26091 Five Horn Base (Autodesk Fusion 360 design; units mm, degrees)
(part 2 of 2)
sketch "Bell Flange Profile" plane through (0, -19.8438, 0) normal (0, -1, 0) x axis (1, 0, 0)
  line L1 (0, 180.975) -> (3.175, 180.975)
  line L2 (0, 176.6094) -> (0, 180.975)
  line L3 (0, 158.8492) -> (0, 166.2906)
  line L4 (0, 108.7438) -> (0, 114.2008)
  line L5 (0, 98.425) -> (0, 100.8063)
  line L6 (2.6536, 98.425) -> (0, 98.425)
  line L7 (14.1513, 108.6076) -> (4.8987, 99.3549)
  line L8 (30.2459, 109.5375) -> (16.3964, 109.5375)
  line L9 (29.9633, 130.2242) -> (35.0084, 127.3114)
  line L10 (9.525, 174.625) -> (9.525, 165.6244)
  line L11 (42.8463, 117.475) -> (42.8463, 114.3)
  line L12 (103.1875, 114.3) -> (42.8463, 114.3)
  line L13 (103.1875, 114.3) -> (103.1875, 117.475)
  line L14 (42.8463, 117.475) -> (103.1875, 117.475)
  curve K1 (39.6962, 120.2531) -> (39.0914, 115.5292)
  line L15 (42.8463, 117.475) -> (42.8463, 114.3)
  line L16 (39.6378, 117.475) -> (42.8463, 117.475)
  line L17 (0, 85.725) -> (0, 98.425)
  line L18 (53.975, 85.725) -> (0, 85.725)
  line L19 (53.975, 117.475) -> (53.975, 85.725)
  circle C1 centre (30.2459, 119.0625) radius 5.1594
  arc A1 centre (3.175, 174.625) radius 6.35 clockwise from (3.175, 180.975) to (9.525, 174.625)
  arc A2 centre (0, 171.45) radius 5.1594 clockwise from (0, 176.6094) to (0, 166.2906)
  arc A3 centre (0, 136.525) radius 22.3242 clockwise from (0, 158.8492) to (0, 114.2008)
  arc A4 centre (0, 104.775) radius 3.9687 clockwise from (0, 108.7438) to (0, 100.8063)
  arc A5 centre (2.6536, 101.6) radius 3.175 clockwise from (4.8987, 99.3549) to (2.6536, 98.425)
  arc A6 centre (16.3964, 106.3625) radius 3.175 clockwise from (14.1513, 108.6076) to (16.3964, 109.5375)
  arc A7 centre (30.2459, 119.0625) radius 9.525 clockwise from (35.0084, 127.3114) to (30.2459, 109.5375)
  arc A8 centre (31.5508, 132.9738) radius 3.175 clockwise from (29.9633, 130.2242) to (28.3957, 133.329)
  arc A9 centre (0, 136.525) radius 28.575 clockwise from (11.43, 162.7144) to (28.3957, 133.329)
  arc A10 centre (12.7, 165.6244) radius 3.175 clockwise from (11.43, 162.7144) to (9.525, 165.6244)
  arc A11 centre (42.8463, 120.65) radius 6.35 clockwise from (42.8463, 114.3) to (39.0914, 115.5292)
  arc A12 centre (42.8463, 120.65) radius 3.175 clockwise from (42.8463, 117.475) to (39.6962, 120.2531)
  point P32 (42.8463, 117.475)
  point P40 (42.8463, 117.475)
  point P41 (39.6378, 117.475)
  point P16 (0, 98.425)
  point P42 (0, 98.425)
  point P45 (53.975, 117.475)
  point P12 (0, 136.525)
  point P43 (0, 85.725)
  coincident P32 P40
  coincident K1 P41
  horizontal L16
  coincident P16 P42
  perpendicular L6 L17
  perpendicular L17 L18
  coincident L14 P45
  perpendicular L14 L19
  dimension "d247" distance P12 P43 = 50.8
  dimension "d248" distance P12 L19 = 53.975 (= "2 1/8")
extrude "Extrude16" add sketch "Bell Flange Profile" profile of L6 A5 L7 A6 L8 A7 L11 L12 L14 K1 A11 L15 A12 L16 L17 L18 L19 blind -6.35 from offset -1.5875 (= "( -1 / 16 ) * 1 in")
fillet "Fillet20" radius 3.175
fillet "Fillet23" radius 0.7937 (= "( 1 / 32 ) * 1 in")
fillet "Fillet24" radius 0.7937 (= "( 1 / 32 ) * 1 in")
fillet "Fillet25" radius 0.3969 (= "( 1 / 64 ) * 1 in")
fillet "Fillet13" radius 1.5875 (= "( 1 / 16 ) * 1 in")
fillet "Fillet15" radius 1.587
fillet "Fillet29" radius 2.381
fillet "Fillet30" radius 1.5875 (= "( 1 / 16 ) * 1 in")
fillet "Fillet31" radius 0.7937 (= "( 1 / 32 ) * 1 in")
mirror "Mirror3" mirrorStitchTolerance 0.1016
delete_face "DeleteFace2"
mirror "Mirror4" mirrorStitchTolerance 0.1016
fillet "Fillet16" radius 1.5875 (= "( 1 / 16 ) * 1 in")
extrude "Extrude11" cut sketch "Bottom Profile" profile of C3 C4 C5 C6 against normal blind 17.4752
offset_faces "OffsetFaces1"
fillet "Fillet18" radius 1.5875 (= "( 1 / 16 ) * 1 in")
sketch "Piping Profile 1" plane through (0, 0, 0) normal (0, 0, -1) x axis (1, 0, 0)
  circle C1 centre (-26.9408, -26.9408) radius 7.1437
  circle C2 centre (26.9408, -26.9408) radius 7.1437
  circle C3 centre (-26.9408, 26.9408) radius 7.1437
  circle C4 centre (26.9408, 26.9408) radius 7.1437
  circle C5 centre (0, 0) radius 50.8
  circle C6 centre (0, 0) radius 9.1281
  circle C7 centre (0, 0) radius 7.1437
  point P1 (0, 0)
  point P7 (0, 0)
  point P8 (0, 0)
  coincident P1 P7
  coincident P1 P8
  dimension "d224" diameter C6 = 18.2563
  dimension "d225" diameter C7 = 14.2875 (= "( 9 / 16 ) * 1 in")
extrude "Extrude12" cut sketch "Piping Profile 1" profile of C6 C7 against normal blind 19.05 (magnitude of "( -3 / 4 ) * 1 in")
extrude "Extrude13" cut sketch "Piping Profile 1" profile of C7 against normal blind 104.775 (magnitude of "-4 1/8")
chamfer "Chamfer1" distance 0.3969 (= "( 1 / 64 ) * 1 in")
sketch "Piping Profile 2" plane through (-303.2959, 0, 0) normal (-1, 0, 0) x axis (0, -1, 0)
  line L1 (-14.2875, 119.0625) -> (14.2875, 119.0625)
  line L2 (-14.2875, 82.55) -> (-14.2875, 119.0625)
  line L3 (14.2875, 82.55) -> (-14.2875, 82.55)
  line L4 (14.2875, 119.0625) -> (14.2875, 82.55)
  line L5 (-17.4625, 82.55) -> (-17.4625, 108.9912)
  line L6 (-17.4625, 82.55) -> (-14.2875, 82.55)
  line L7 (-14.2875, 119.0625) -> (-14.2875, 82.55)
  line L8 (-14.2875, 82.55) -> (-14.2875, 79.375)
  line L9 (-17.4625, 82.55) -> (-14.2875, 82.55)
  line L10 (-14.2875, 82.55) -> (14.2875, 82.55)
  line L11 (-14.2875, 82.55) -> (-14.2875, 79.375)
  line L12 (14.2875, 79.375) -> (-14.2875, 79.375)
  line L13 (14.2875, 82.55) -> (14.2875, 79.375)
  line L14 (14.2875, 82.55) -> (14.2875, 119.0625)
  line L15 (17.4625, 82.55) -> (14.2875, 82.55)
  line L16 (17.4625, 108.9912) -> (17.4625, 82.55)
  line L17 (17.4625, 82.55) -> (14.2875, 82.55)
  line L18 (14.2875, 82.55) -> (14.2875, 79.375)
  line L19 (19.8438, 109.5375) -> (19.8438, 127.3114)
  line L20 (3.6404, 127.3114) -> (19.8438, 127.3114)
  curve K1 (2.3812, 126.9064) -> (3.6404, 127.3114)
  line L21 (-2.3812, 126.9064) -> (2.3812, 126.9064)
  curve K2 (-2.3812, 126.9064) -> (-3.6404, 127.3114)
  line L22 (-19.8438, 127.3114) -> (-3.6404, 127.3114)
  line L23 (-19.8438, 109.5375) -> (-19.8438, 127.3114)
  line L24 (14.2875, 119.0625) -> (-14.2875, 119.0625)
  line L25 (0, 119.0625) -> (0, 79.375)
  curve K3 (-14.2875, 119.0625) -> (-17.4625, 108.9912)
  curve K4 (14.2875, 119.0625) -> (17.4625, 108.9912)
  curve K5 (19.8435, 111.0053) -> (14.2875, 119.0625)
  curve K6 (-19.8435, 111.0053) -> (-14.2875, 119.0625)
  line L26 (19.8435, 111.0053) -> (19.8435, 109.5375)
  line L27 (19.8438, 109.5375) -> (19.8435, 109.5375)
  line L28 (-19.8435, 109.5375) -> (-19.8438, 109.5375)
  line L29 (-19.8435, 111.0053) -> (-19.8435, 109.5375)
  arc A1 centre (-14.2875, 82.55) radius 3.175 clockwise from (-14.2875, 79.375) to (-17.4625, 82.55)
  arc A2 centre (14.2875, 82.55) radius 3.175 clockwise from (17.4625, 82.55) to (14.2875, 79.375)
  circle C1 centre (0, 101.6) radius 7.1437
  point P34 (0, 79.375)
  point P36 (0, 101.6)
  point P35 (0, 119.0625)
  midpoint L12 P34
  perpendicular L10 L25
  coincident L25 P36
  coincident L24 P35
  dimension "d231" diameter C1 = 14.2875 (= "( 9 / 16 ) * 1 in")
  dimension "d232" distance L12 P36 = 22.225 (= "( 7 / 8 ) * 1 in")
extrude "Extrude14" cut sketch "Piping Profile 2" profile of C1 against normal blind 606.6028
sketch "Piping Profile 3" plane through (0, 0, 0) normal (0, 0, -1) x axis (1, 0, 0)
  line L1 (-95.0806, 35.279) -> (-31.1922, 42.6427)
  line L2 (-111.1939, 47.7175) -> (-101.7641, 37.7185)
  line L3 (-125.0095, 49.2125) -> (-114.6586, 49.2125)
  line L4 (-133.6665, 35.1345) -> (-129.4584, 46.1496)
  line L5 (-136.5547, -31.4469) -> (-136.5547, 31.4469)
  line L6 (-129.4584, -46.1496) -> (-133.6665, -35.1345)
  line L7 (-114.6586, -49.2125) -> (-125.0095, -49.2125)
  line L8 (-101.7641, -37.7185) -> (-111.1939, -47.7175)
  line L9 (-31.1922, -42.6427) -> (-95.0806, -35.279)
  line L10 (95.0806, -35.279) -> (31.1922, -42.6427)
  line L11 (111.1939, -47.7175) -> (101.7641, -37.7185)
  line L12 (125.0095, -49.2125) -> (114.6586, -49.2125)
  line L13 (133.6665, -35.1345) -> (129.4584, -46.1496)
  line L14 (136.5547, 31.4469) -> (136.5547, -31.4469)
  line L15 (129.4584, 46.1496) -> (133.6665, 35.1345)
  line L16 (114.6586, 49.2125) -> (125.0095, 49.2125)
  line L17 (101.7641, 37.7185) -> (111.1939, 47.7175)
  line L18 (31.1922, 42.6427) -> (95.0806, 35.279)
  line L19 (120.65, 0) -> (0, 0)
  line L20 (-120.65, 0) -> (0, 0)
  circle C1 centre (0, 0) radius 50.8
  circle C2 centre (26.9408, 26.9408) radius 7.1437
  circle C3 centre (-26.9408, 26.9408) radius 7.1437
  circle C4 centre (26.9408, -26.9408) radius 7.1437
  circle C5 centre (-26.9408, -26.9408) radius 7.1437
  circle C6 centre (0, 0) radius 9.525
  arc A1 centre (0, 0) radius 52.8332 clockwise from (-31.1922, -42.6427) to (-31.1922, 42.6427)
  arc A2 centre (-95.9895, 43.1643) radius 7.9375 clockwise from (-95.0806, 35.279) to (-101.7641, 37.7185)
  arc A3 centre (-114.6586, 44.45) radius 4.7625 clockwise from (-114.6586, 49.2125) to (-111.1939, 47.7175)
  arc A4 centre (-125.0095, 44.45) radius 4.7625 clockwise from (-129.4584, 46.1496) to (-125.0095, 49.2125)
  arc A5 centre (-141.0813, 37.9671) radius 7.9375 clockwise from (-133.6665, 35.1345) to (-136.5547, 31.4469)
  arc A6 centre (-141.0813, -37.9671) radius 7.9375 clockwise from (-136.5547, -31.4469) to (-133.6665, -35.1345)
  arc A7 centre (-125.0095, -44.45) radius 4.7625 clockwise from (-125.0095, -49.2125) to (-129.4584, -46.1496)
  arc A8 centre (-114.6586, -44.45) radius 4.7625 clockwise from (-111.1939, -47.7175) to (-114.6586, -49.2125)
  arc A9 centre (-95.9895, -43.1643) radius 7.9375 clockwise from (-101.7641, -37.7185) to (-95.0806, -35.279)
  arc A10 centre (0, 0) radius 52.8332 clockwise from (31.1922, 42.6427) to (31.1922, -42.6427)
  arc A11 centre (95.9895, -43.1643) radius 7.9375 clockwise from (95.0806, -35.279) to (101.7641, -37.7185)
  arc A12 centre (114.6586, -44.45) radius 4.7625 clockwise from (114.6586, -49.2125) to (111.1939, -47.7175)
  arc A13 centre (125.0095, -44.45) radius 4.7625 clockwise from (129.4584, -46.1496) to (125.0095, -49.2125)
  arc A14 centre (141.0813, -37.9671) radius 7.9375 clockwise from (133.6665, -35.1345) to (136.5547, -31.4469)
  arc A15 centre (141.0813, 37.9671) radius 7.9375 clockwise from (136.5547, 31.4469) to (133.6665, 35.1345)
  arc A16 centre (125.0095, 44.45) radius 4.7625 clockwise from (125.0095, 49.2125) to (129.4584, 46.1496)
  arc A17 centre (114.6586, 44.45) radius 4.7625 clockwise from (111.1939, 47.7175) to (114.6586, 49.2125)
  arc A18 centre (95.9895, 43.1643) radius 7.9375 clockwise from (101.7641, 37.7185) to (95.0806, 35.279)
  circle C7 centre (120.65, 0) radius 7.1437
  circle C8 centre (-120.65, 0) radius 7.1437
  point P9 (0, 0)
  point P61 (0, 0)
  point P62 (120.65, 0)
  point P63 (120.65, 0)
  point P64 (-120.65, 0)
  point P65 (-120.65, 0)
  coincident P9 P61
  horizontal L19
  coincident P62 P63
  parallel L19 L20
  coincident P64 P65
  dimension "d235" diameter C7 = 14.2875 (= "( 9 / 16 ) * 1 in")
  dimension "d236" distance P61 P62 = 120.65 (= "4 3/4")
  dimension "d237" distance P61 P64 = 120.65 (= "4 3/4")
  dimension "d238" diameter C8 = 14.2875 (= "( 9 / 16 ) * 1 in")
extrude "Extrude15" cut sketch "Piping Profile 3" profile of C7 C8 against normal blind 180.975 (magnitude of "-7 1/8")
sketch "Main Profile" plane through (0, 0, 0) normal (0, 1, 0) x axis (1, 0, 0)
  line L1 (303.2959, -108.7438) -> (303.2959, -94.4563)
  line L2 (304.8834, -101.6) -> (303.2959, -101.6)
  line L3 (304.8834, -104.9766) -> (304.8834, -101.6)
  line L4 (303.2959, -108.7438) -> (303.2959, -111.125)
  line L5 (300.1209, -108.7438) -> (303.2959, -108.7438)
  line L6 (300.1209, -101.6) -> (300.1209, -108.7438)
  line L7 (303.2959, -101.6) -> (300.1209, -101.6)
  arc A1 centre (298.5334, -104.9766) radius 6.35 clockwise from (304.8834, -104.9766) to (304.0897, -108.0508)
  arc A2 centre (309.6459, -111.125) radius 6.35 clockwise from (303.2959, -111.125) to (304.0897, -108.0508)
  point P4 (303.2959, -101.6)
  point P3 (303.2959, -108.7438)
  point P11 (303.2959, -108.7438)
  point P12 (303.2959, -108.7438)
  point P5 (304.8834, -101.6)
  point P14 (300.1209, -101.6)
  point P9 (303.2959, -111.125)
  midpoint L1 P4
  perpendicular L1 L2
  perpendicular L2 L3
  tangent L3 A1
  tangent A1 A2
  coincident P3 P11
  vertical L4
  tangent A2 L4
  coincident P3 P12
  perpendicular L1 L5
  perpendicular L5 L6
  perpendicular L1 L7
  dimension "d241" radius A2 = 6.35 (= "( 1 / 4 ) * 1 in")
  dimension "d242" radius A1 = 6.35 (= "d241")
  dimension "d243" distance P4 P5 = 1.5875 (= "( 1 / 16 ) * 1 in")
  dimension "d244" distance P4 P14 = 3.175 (= "( 1 / 8 ) * 1 in")
  dimension "d246" distance L2 P9 = 9.525 (= "( 3 / 8 ) * 1 in")
revolve "Revolve1" sketch "Main Profile" AlongAngle 360 bodies "Plug Weld"
copy_paste "CopyPaste1"
copy_paste "CopyPaste2"
copy_paste "CopyPaste3"
sketch "Logo Reference Profile" plane through (0, -3.9688, 0) normal (0, -1, 0) x axis (1, 0, 0)
  line L1 (-12.7, 174.625) -> (-12.7, 165.6244)
  line L2 (-6.35, 247.65) -> (-6.35, 183.6053)
  line L3 (-107.95, 247.65) -> (-6.35, 247.65)
  line L4 (-107.95, 241.8244) -> (-107.95, 247.65)
  line L5 (-22.225, 227.0125) -> (-80.9625, 227.0125)
  line L6 (-14.2875, 165.7971) -> (-14.2875, 219.075)
  line L7 (0, 257.175) -> (0, 0)
  line L8 (-107.95, 237.3313) -> (0, 237.3313)
  line L9 (-51.5938, 247.65) -> (-51.5938, 227.0125)
  curve K1 (-39.2108, 245.6028) -> (-36.6944, 246.6703)
  curve K2 (-39.477, 245.3558) -> (-39.2108, 245.6028)
  line L10 (-39.5346, 245.2598) -> (-39.477, 245.3558)
  line L11 (-39.5346, 237.7327) -> (-39.5346, 245.2598)
  curve K3 (-39.4907, 230.1096) -> (-39.5346, 237.7327)
  curve K4 (-39.2026, 229.8516) -> (-39.4907, 230.1096)
  curve K5 (-38.2668, 229.4702) -> (-39.2026, 229.8516)
  curve K6 (-35.9398, 228.3561) -> (-38.2668, 229.4702)
  curve K7 (-35.6105, 228.2326) -> (-35.9398, 228.3561)
  curve K8 (-35.1879, 228.4603) -> (-35.6105, 228.2326)
  line L12 (-35.1029, 228.5674) -> (-35.1879, 228.4603)
  line L13 (-35.0946, 229.097) -> (-35.1029, 228.5674)
  curve K9 (-35.1276, 229.7089) -> (-35.0946, 229.097)
  curve K10 (-35.391, 229.9614) -> (-35.1276, 229.7089)
  curve K11 (-36.9551, 230.6062) -> (-35.391, 229.9614)
  curve K12 (-37.6686, 231.0261) -> (-36.9551, 230.6062)
  curve K13 (-37.696, 231.059) -> (-37.6686, 231.0261)
  curve K14 (-37.7729, 233.8388) -> (-37.696, 231.059)
  line L14 (-37.7646, 236.3991) -> (-37.7729, 233.8388)
  line L15 (-37.6906, 236.5143) -> (-37.7646, 236.3991)
  curve K15 (-37.1637, 236.7421) -> (-37.6906, 236.5143)
  curve K16 (-36.7685, 236.8052) -> (-37.1637, 236.7421)
  curve K17 (-36.5161, 237.1263) -> (-36.7685, 236.8052)
  curve K18 (-36.4886, 237.1921) -> (-36.5161, 237.1263)
  curve K19 (-36.4612, 237.5488) -> (-36.4886, 237.1921)
  curve K20 (-36.6588, 238.1992) -> (-36.4612, 237.5488)
  curve K21 (-37.1308, 238.3474) -> (-36.6588, 238.1992)
  curve K22 (-37.6823, 238.5998) -> (-37.1308, 238.3474)
  line L16 (-37.7646, 238.7206) -> (-37.6823, 238.5998)
  line L17 (-37.7729, 241.4812) -> (-37.7646, 238.7206)
  curve K23 (-37.7537, 244.3405) -> (-37.7729, 241.4812)
  curve K24 (-36.5024, 245.1116) -> (-37.7537, 244.3405)
  curve K25 (-35.3581, 245.6796) -> (-36.5024, 245.1116)
  curve K26 (-35.1989, 246.2724) -> (-35.3581, 245.6796)
  curve K27 (-35.3306, 246.8569) -> (-35.1989, 246.2724)
  curve K28 (-35.7203, 247.0297) -> (-35.3306, 246.8569)
  curve K29 (-36.6944, 246.6703) -> (-35.7203, 247.0297)
  curve K30 (-67.412, 246.4206) -> (-67.1266, 246.7498)
  curve K31 (-67.4422, 237.3046) -> (-67.412, 246.4206)
  curve K32 (-67.2913, 227.9801) -> (-67.4422, 237.3046)
  curve K33 (-66.6821, 227.8896) -> (-67.2913, 227.9801)
  curve K34 (-65.9686, 228.2298) -> (-66.6821, 227.8896)
  curve K35 (-63.8611, 229.1628) -> (-65.9686, 228.2298)
  curve K36 (-62.887, 229.6458) -> (-63.8611, 229.1628)
  curve K37 (-62.8321, 230.1974) -> (-62.887, 229.6458)
  curve K38 (-63.0489, 230.9054) -> (-62.8321, 230.1974)
  curve K39 (-63.3343, 230.9877) -> (-63.0489, 230.9054)
  curve K40 (-64.2865, 230.6748) -> (-63.3343, 230.9877)
  curve K41 (-65.1975, 230.351) -> (-64.2865, 230.6748)
  curve K42 (-65.6311, 230.5925) -> (-65.1975, 230.351)
  curve K43 (-65.686, 238.2815) -> (-65.6311, 230.5925)
  curve K44 (-65.7381, 245.9733) -> (-65.686, 238.2815)
  curve K45 (-65.8561, 246.1544) -> (-65.7381, 245.9733)
  curve K46 (-66.748, 246.7636) -> (-65.8561, 246.1544)
  curve K47 (-67.1266, 246.7498) -> (-66.748, 246.7636)
  curve K48 (-42.8001, 244.2582) -> (-42.3418, 244.4503)
  curve K49 (-42.9236, 244.0826) -> (-42.8001, 244.2582)
  curve K50 (-42.9373, 237.5077) -> (-42.9236, 244.0826)
  curve K51 (-42.8687, 230.9685) -> (-42.9373, 237.5077)
  curve K52 (-42.3199, 230.6337) -> (-42.8687, 230.9685)
  curve K53 (-41.9275, 230.502) -> (-42.3199, 230.6337)
  curve K54 (-41.7546, 230.491) -> (-41.9275, 230.502)
  curve K55 (-41.3704, 230.7627) -> (-41.7546, 230.491)
  curve K56 (-41.321, 230.8669) -> (-41.3704, 230.7627)
  curve K57 (-41.321, 237.4802) -> (-41.321, 230.8669)
  curve K58 (-41.3704, 244.2006) -> (-41.321, 237.4802)
  curve K59 (-41.6284, 244.5299) -> (-41.3704, 244.2006)
  curve K60 (-42.3418, 244.4503) -> (-41.6284, 244.5299)
  curve K61 (-61.2899, 244.3048) -> (-61.0978, 244.475)
  line L18 (-61.364, 244.1923) -> (-61.2899, 244.3048)
  line L19 (-61.3722, 237.3485) -> (-61.364, 244.1923)
  line L20 (-61.3777, 230.502) -> (-61.3722, 237.3485)
  line L21 (-61.3201, 230.3812) -> (-61.3777, 230.502)
  curve K62 (-60.8728, 230.1123) -> (-61.3201, 230.3812)
  curve K63 (-60.1978, 230.3346) -> (-60.8728, 230.1123)
  curve K64 (-58.8367, 230.7791) -> (-60.1978, 230.3346)
  curve K65 (-57.4921, 231.0865) -> (-58.8367, 230.7791)
  curve K66 (-56.8252, 231.2429) -> (-57.4921, 231.0865)
  curve K67 (-56.5838, 231.4624) -> (-56.8252, 231.2429)
  curve K68 (-56.5261, 232.0003) -> (-56.5838, 231.4624)
  curve K69 (-56.6085, 232.4914) -> (-56.5261, 232.0003)
  curve K70 (-56.9762, 232.7082) -> (-56.6085, 232.4914)
  curve K71 (-58.2906, 232.4064) -> (-56.9762, 232.7082)
  curve K72 (-59.3251, 232.1649) -> (-58.2906, 232.4064)
  curve K73 (-59.6599, 232.4887) -> (-59.3251, 232.1649)
  curve K74 (-59.6764, 234.3904) -> (-59.6599, 232.4887)
  line L22 (-59.6764, 236.2042) -> (-59.6764, 234.3904)
  line L23 (-59.6133, 236.3112) -> (-59.6764, 236.2042)
  curve K75 (-59.0919, 236.5418) -> (-59.6133, 236.3112)
  curve K76 (-58.705, 236.6186) -> (-59.0919, 236.5418)
  curve K77 (-58.4141, 237.3924) -> (-58.705, 236.6186)
  curve K78 (-58.5101, 237.8699) -> (-58.4141, 237.3924)
  curve K79 (-59.0315, 238.1224) -> (-58.5101, 237.8699)
  curve K80 (-59.5776, 238.2705) -> (-59.0315, 238.1224)
  curve K81 (-59.7038, 238.5312) -> (-59.5776, 238.2705)
  curve K82 (-59.7285, 238.6218) -> (-59.7038, 238.5312)
  curve K83 (-59.7971, 241.8598) -> (-59.7285, 238.6218)
  curve K84 (-59.5721, 242.4059) -> (-59.7971, 241.8598)
  curve K85 (-58.9766, 242.4334) -> (-59.5721, 242.4059)
  curve K86 (-57.2259, 242.1672) -> (-58.9766, 242.4334)
  curve K87 (-56.8445, 242.3977) -> (-57.2259, 242.1672)
  curve K88 (-56.7731, 242.8669) -> (-56.8445, 242.3977)
  curve K89 (-56.8335, 243.3526) -> (-56.7731, 242.8669)
  curve K90 (-57.1381, 243.5996) -> (-56.8335, 243.3526)
  curve K91 (-58.1122, 243.778) -> (-57.1381, 243.5996)
  curve K92 (-59.8877, 244.2362) -> (-58.1122, 243.778)
  curve K93 (-60.8563, 244.5244) -> (-59.8877, 244.2362)
  curve K94 (-61.0978, 244.475) -> (-60.8563, 244.5244)
  curve K95 (-49.0731, 243.0096) -> (-48.7438, 243.3225)
  curve K96 (-49.1143, 242.8971) -> (-49.0731, 243.0096)
  curve K97 (-49.139, 237.5543) -> (-49.1143, 242.8971)
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  point P1 (0, 0)
  point P19 (0, 0)
  point P21 (0, 237.3313)
  point P22 (-107.95, 237.3313)
  point P23 (-51.5938, 227.0125)
  point P24 (-51.5938, 247.65)
  point P25 (-51.5938, 237.3313)
  point P20 (0, 257.175)
  coincident P1 P19
  vertical L7
  coincident L7 P21
  perpendicular L7 L8
  coincident L4 P22
  midpoint L5 P23
  coincident L3 P24
  perpendicular L5 L9
  midpoint L9 P25
  coincident L8 P25
  dimension "d275" distance P19 P20 = 257.175 (= "10 1/8")
sketch "Text Profile 1" plane through (0, -3.9688, 0) normal (0, -1, 0) x axis (1, 0, 0)
  line L1 (-12.7, 174.625) -> (-12.7, 165.6244)
  line L2 (-6.35, 247.65) -> (-6.35, 183.6053)
  line L3 (-107.95, 247.65) -> (-6.35, 247.65)
  line L4 (-107.95, 241.8244) -> (-107.95, 247.65)
  line L5 (-22.225, 227.0125) -> (-80.9625, 227.0125)
  line L6 (-14.2875, 165.7971) -> (-14.2875, 219.075)
  line L7 (-51.5938, 247.65) -> (-51.5938, 227.0125)
  line L8 (-107.95, 237.3313) -> (0, 237.3313)
  line L9 (-67.4223, 228.7115) -> (-67.4223, 246.2077)
  line L10 (-65.9127, 246.1956) -> (-66.5663, 246.6533)
  line L11 (-65.6999, 230.9186) -> (-65.6999, 245.7868)
  line L12 (-63.246, 229.362) -> (-66.1059, 227.9048)
  line L13 (-62.8318, 230.4246) -> (-62.8318, 230.0379)
  line L14 (-64.8931, 230.4242) -> (-63.7672, 230.9979)
  line L15 (-61.382, 230.8537) -> (-61.382, 243.9436)
  line L16 (-57.2043, 243.6243) -> (-60.706, 244.475)
  line L17 (-56.7698, 242.6744) -> (-56.7698, 243.0716)
  line L18 (-58.8781, 242.4647) -> (-57.4713, 242.1229)
  line L19 (-59.7945, 238.6398) -> (-59.7945, 241.7443)
  line L20 (-58.9219, 238.1303) -> (-59.285, 238.1303)
  line L21 (-58.4124, 237.0523) -> (-58.4124, 237.6208)
  line L22 (-59.285, 236.5428) -> (-58.9219, 236.5428)
  line L23 (-59.7945, 232.8589) -> (-59.7945, 236.0333)
  line L24 (-59.7945, 238.6398) -> (-59.7945, 236.0333)
  line L25 (-56.9292, 231.2025) -> (-60.5046, 230.1902)
  line L26 (-56.5279, 232.1884) -> (-56.5279, 231.7331)
  line L27 (-58.9124, 232.1919) -> (-57.1809, 232.6822)
  line L28 (-51.4611, 243.1154) -> (-54.6768, 243.1154)
  line L29 (-51.0453, 241.0963) -> (-51.0453, 242.6995)
  line L30 (-52.3968, 241.6002) -> (-52.2986, 240.9952)
  line L31 (-53.3927, 241.9401) -> (-52.7963, 241.9401)
  line L32 (-53.7974, 241.3086) -> (-53.7974, 241.5354)
  line L33 (-55.1727, 240.0742) -> (-55.1727, 242.6195)
  line L34 (-52.5808, 236.3806) -> (-55.0362, 239.6637)
  line L35 (-53.7974, 240.886) -> (-53.7974, 241.3086)
  line L36 (-50.9933, 236.9085) -> (-53.6609, 240.4755)
  line L37 (-50.6771, 232.0593) -> (-50.6771, 235.9578)
  line L38 (-52.2646, 233.2425) -> (-52.2646, 235.4298)
  line L39 (-54.6739, 231.6625) -> (-51.074, 231.6625)
  line L40 (-55.0708, 235.4034) -> (-55.0708, 232.0593)
  line L41 (-54.2924, 235.8003) -> (-54.6739, 235.8003)
  line L42 (-53.8955, 233.2425) -> (-53.8955, 235.4034)
  line L43 (-52.6693, 232.8378) -> (-53.4908, 232.8378)
  line L44 (-49.1272, 232.4584) -> (-49.1272, 242.9431)
  line L45 (-47.9365, 243.34) -> (-48.7303, 243.34)
  line L46 (-47.5397, 233.5088) -> (-47.5397, 242.9431)
  line L47 (-44.8755, 231.2241) -> (-48.4323, 231.6708)
  line L48 (-44.4292, 232.4179) -> (-44.4292, 231.6179)
  line L49 (-47.1922, 233.115) -> (-44.7766, 232.8117)
  line L50 (-42.926, 231.1293) -> (-42.926, 243.9479)
  line L51 (-41.8646, 230.4807) -> (-42.6583, 230.754)
  line L52 (-41.3385, 244.2212) -> (-41.3385, 230.856)
  line L53 (-42.6583, 244.3232) -> (-41.8646, 244.5965)
  line L54 (-39.5313, 230.589) -> (-39.5313, 244.9325)
  line L55 (-35.7413, 247.0593) -> (-39.0463, 245.6637)
  line L56 (-35.19, 245.832) -> (-35.19, 246.6936)
  line L57 (-37.5665, 244.5654) -> (-35.4325, 245.4664)
  line L58 (-37.809, 238.5219) -> (-37.809, 244.1998)
  line L59 (-36.8562, 238.125) -> (-37.4121, 238.125)
  line L60 (-36.4594, 236.9344) -> (-36.4594, 237.7281)
  line L61 (-37.4121, 236.5375) -> (-36.8562, 236.5375)
  line L62 (-37.809, 231.2905) -> (-37.809, 236.1406)
  line L63 (-37.809, 238.5219) -> (-37.809, 236.1406)
  line L64 (-35.3229, 229.8947) -> (-37.5777, 230.9299)
  line L65 (-35.0916, 228.6606) -> (-35.0916, 229.534)
  line L66 (-39.0687, 229.8676) -> (-35.654, 228.3)
  line L67 (0, 257.175) -> (0, 0)
  line L68 (107.95, 237.3313) -> (0, 237.3313)
  line L69 (14.2875, 219.075) -> (14.2875, 165.7971)
  line L70 (80.9625, 227.0125) -> (22.225, 227.0125)
  line L71 (107.95, 247.65) -> (107.95, 241.8244)
  line L72 (6.35, 247.65) -> (107.95, 247.65)
  line L73 (6.35, 183.6053) -> (6.35, 247.65)
  line L74 (12.7, 165.6244) -> (12.7, 174.625)
  line L75 (97.2243, 234.1562) -> (6.35, 234.1563)
  line L76 (51.6936, 232.5688) -> (14.329, 232.5688)
  line L77 (51.6936, 231.3781) -> (51.6936, 232.5688)
  line L78 (14.329, 231.3781) -> (51.6936, 231.3781)
  line L79 (14.329, 232.5688) -> (14.329, 231.3781)
  line L80 (14.329, 237.3313) -> (14.329, 232.5688)
  line L81 (51.6936, 237.3313) -> (51.6936, 232.5688)
  line L82 (-88.9, 219.075) -> (-88.9, 212.725)
  line L83 (88.9, 212.725) -> (88.9, 219.075)
  arc A1 centre (-19.05, 165.7971) radius 4.7625 clockwise from (-14.2875, 165.7971) to (-14.3871, 164.8283)
  arc A2 centre (0, 136.525) radius 31.75 clockwise from (-14.3871, 164.8283) to (-12.7, 165.6244)
  arc A3 centre (-3.175, 174.625) radius 9.525 clockwise from (-12.7, 174.625) to (-6.35, 183.6053)
  arc A4 centre (-120.65, 212.725) radius 31.75 clockwise from (-107.95, 241.8244) to (-88.9, 212.725)
  arc A5 centre (-22.225, 219.075) radius 7.9375 clockwise from (-22.225, 227.0125) to (-14.2875, 219.075)
  arc A6 centre (-66.8783, 246.2077) radius 0.5439 clockwise from (-67.4223, 246.2077) to (-66.5663, 246.6533)
  arc A7 centre (-66.1989, 245.7868) radius 0.499 clockwise from (-65.9127, 246.1956) to (-65.6999, 245.7868)
  arc A8 centre (-66.5169, 228.7115) radius 0.9053 clockwise from (-66.1059, 227.9048) to (-67.4223, 228.7115)
  arc A9 centre (-63.5904, 230.0379) radius 0.7586 clockwise from (-62.8318, 230.0379) to (-63.246, 229.362)
  arc A10 centre (-63.4751, 230.4246) radius 0.6433 clockwise from (-63.7672, 230.9979) to (-62.8318, 230.4246)
  arc A11 centre (-65.145, 230.9186) radius 0.5549 clockwise from (-64.8931, 230.4242) to (-65.6999, 230.9186)
  arc A12 centre (-60.8351, 243.9436) radius 0.5469 clockwise from (-61.382, 243.9436) to (-60.706, 244.475)
  arc A13 centre (-57.3386, 243.0716) radius 0.5688 clockwise from (-57.2043, 243.6243) to (-56.7698, 243.0716)
  arc A14 centre (-57.3373, 242.6744) radius 0.5676 clockwise from (-56.7698, 242.6744) to (-57.4713, 242.1229)
  arc A15 centre (-59.0531, 241.7443) radius 0.7413 clockwise from (-59.7945, 241.7443) to (-58.8781, 242.4647)
  arc A16 centre (-59.285, 238.6398) radius 0.5095 clockwise from (-59.285, 238.1303) to (-59.7945, 238.6398)
  arc A17 centre (-58.9219, 237.6208) radius 0.5095 clockwise from (-58.9219, 238.1303) to (-58.4124, 237.6208)
  arc A18 centre (-58.9219, 237.0523) radius 0.5095 clockwise from (-58.4124, 237.0523) to (-58.9219, 236.5428)
  arc A19 centre (-59.285, 236.0333) radius 0.5095 clockwise from (-59.7945, 236.0333) to (-59.285, 236.5428)
  arc A20 centre (-60.6924, 230.8537) radius 0.6896 clockwise from (-60.5046, 230.1902) to (-61.382, 230.8537)
  arc A21 centre (-57.0794, 231.7331) radius 0.5515 clockwise from (-56.5279, 231.7331) to (-56.9292, 231.2025)
  arc A22 centre (-57.0411, 232.1884) radius 0.5132 clockwise from (-57.1809, 232.6822) to (-56.5279, 232.1884)
  arc A23 centre (-59.1013, 232.8589) radius 0.6932 clockwise from (-58.9124, 232.1919) to (-59.7945, 232.8589)
  arc A24 centre (-51.4611, 242.6995) radius 0.4159 clockwise from (-51.4611, 243.1154) to (-51.0453, 242.6995)
  arc A25 centre (-51.676, 241.0963) radius 0.6307 clockwise from (-51.0453, 241.0963) to (-52.2986, 240.9952)
  arc A26 centre (-52.7963, 241.5354) radius 0.4047 clockwise from (-52.7963, 241.9401) to (-52.3968, 241.6002)
  arc A27 centre (-53.3927, 241.5354) radius 0.4047 clockwise from (-53.7974, 241.5354) to (-53.3927, 241.9401)
  arc A28 centre (-54.6768, 242.6195) radius 0.4959 clockwise from (-55.1727, 242.6195) to (-54.6768, 243.1154)
  arc A29 centre (-54.4873, 240.0742) radius 0.6854 clockwise from (-55.0362, 239.6637) to (-55.1727, 240.0742)
  arc A30 centre (-53.112, 240.886) radius 0.6854 clockwise from (-53.6609, 240.4755) to (-53.7974, 240.886)
  arc A31 centre (-52.2646, 235.9578) radius 1.5875 clockwise from (-50.9933, 236.9085) to (-50.6771, 235.9578)
  arc A32 centre (-53.8521, 235.4298) radius 1.5875 clockwise from (-52.5808, 236.3806) to (-52.2646, 235.4298)
  arc A33 centre (-51.074, 232.0593) radius 0.3969 clockwise from (-50.6771, 232.0593) to (-51.074, 231.6625)
  arc A34 centre (-54.6739, 232.0593) radius 0.3969 clockwise from (-54.6739, 231.6625) to (-55.0708, 232.0593)
  arc A35 centre (-54.6739, 235.4034) radius 0.3969 clockwise from (-55.0708, 235.4034) to (-54.6739, 235.8003)
  arc A36 centre (-54.2924, 235.4034) radius 0.3969 clockwise from (-54.2924, 235.8003) to (-53.8955, 235.4034)
  arc A37 centre (-53.4908, 233.2425) radius 0.4047 clockwise from (-53.4908, 232.8378) to (-53.8955, 233.2425)
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  point P30 (-65.6999, 230.9186)
  point P40 (-65.6999, 230.9186)
  point P131 (-47.5397, 233.5088)
  point P141 (-47.5397, 233.5088)
  point P181 (-36.4594, 237.3313)
  point P156 (-39.5313, 230.589)
  point P191 (-39.5313, 230.589)
  point P21 (0, 237.3313)
  point P195 (0, 237.3313)
  point P22 (-107.95, 237.3313)
  point P196 (107.95, 237.3313)
  point P214 (6.35, 234.1563)
  point P220 (14.329, 237.3313)
  point P221 (51.6936, 237.3313)
  point P216 (14.329, 232.5688)
  point P219 (14.329, 231.3781)
  perpendicular L8 L9
  tangent L9 A6
  tangent A6 L10
  tangent L10 A7
  tangent A7 L11
  vertical L11
  tangent L9 A8
  tangent A8 L12
  tangent L12 A9
  vertical L13
  tangent A9 L13
  tangent L13 A10
  tangent A10 L14
  parallel L12 L14
  tangent L14 A11
  coincident P30 P40
  tangent L11 A11
  vertical L15
  tangent L15 A12
  tangent A12 L16
  tangent L16 A13
  tangent A13 L17
  vertical L17
  tangent L17 A14
  tangent A14 L18
  parallel L16 L18
  tangent L18 A15
  vertical L19
  tangent A15 L19
  tangent L19 A16
  tangent A16 L20
  horizontal L20
  tangent L20 A17
  tangent A17 L21
  vertical L21
  tangent L21 A18
  horizontal L22
  tangent A18 L22
  tangent L22 A19
  vertical L23
  tangent A19 L23
  vertical L24
  tangent L15 A20
  tangent A20 L25
  tangent L25 A21
  vertical L26
  tangent A21 L26
  tangent L26 A22
  tangent A22 L27
  tangent L27 A23
  tangent L23 A23
  parallel L25 L27
  horizontal L28
  tangent L28 A24
  vertical L29
  tangent A24 L29
  tangent L29 A25
  tangent A25 L30
  tangent L30 A26
  tangent A26 L31
  horizontal L31
  tangent L31 A27
  vertical L32
  tangent A27 L32
  tangent L28 A28
  vertical L33
  tangent A28 L33
  tangent L33 A29
  tangent A29 L34
  parallel L32 L35
  tangent L35 A30
  tangent A30 L36
  parallel L34 L36
  tangent L36 A31
  vertical L37
  tangent A31 L37
  tangent L34 A32
  tangent A32 L38
  vertical L38
  tangent L37 A33
  horizontal L39
  tangent A33 L39
  tangent L39 A34
  vertical L40
  tangent A34 L40
  tangent L40 A35
  horizontal L41
  tangent A35 L41
  tangent L41 A36
  vertical L42
  tangent A36 L42
  tangent L42 A37
  perpendicular L7 L43
  tangent A37 L43
  vertical L44
  horizontal L45
  vertical L46
  vertical L48
  parallel L47 L49
  coincident P131 P141
  vertical L50
  vertical L52
  perpendicular L3 L54
  vertical L56
  parallel L55 L57
  vertical L58
  horizontal L59
  vertical L60
  horizontal L61
  vertical L62
  vertical L63
  midpoint L60 P181
  coincident L8 P181
  vertical L65
  parallel L64 L66
  coincident P156 P191
  symmetric P21 L67 P195
  symmetric P22 L67 P196
  coincident L73 P214
  perpendicular L73 L75
  horizontal L76
  vertical L77
  horizontal L78
  vertical L79
  coincident L68 P220
  perpendicular L68 L80
  coincident L68 P221
  perpendicular L68 L81
  dimension "d277" angle L9 L10 = 55
  dimension "d278" distance L9 L11 = 1.7223
  dimension "d279" angle L9 L12 = 63
  dimension "d280" distance L15 L19 = 1.5875 (= "( 1 / 16 ) * 1 in")
  dimension "d281" radius A17 = 0.5095
  dimension "d282" radius A16 = 0.5095 (= "d281")
  dimension "d283" radius A18 = 0.5095 (= "d281")
  dimension "d284" radius A19 = 0.5095 (= "d281")
  dimension "d285" distance L20 L22 = 1.5875 (= "( 1 / 16 ) * 1 in")
  dimension "d287" radius A24 = 0.4159
  dimension "d288" angle L29 L30 = 9.219
  dimension "d289" radius A25 = 0.6307
  dimension "d290" radius A26 = 0.4047
  dimension "d291" radius A27 = 0.4047 (= "d290")
  dimension "d292" radius A29 = 0.6854
  dimension "d293" radius A30 = 0.6854 (= "d292")
  dimension "d294" distance L34 L36 = 1.5875 (= "( 1 / 16 ) * 1 in")
  dimension "d295" distance L37 L38 = 1.5875 (= "( 1 / 16 ) * 1 in")
  dimension "d296" radius A32 = 1.5875 (= "( 1 / 16 ) * 1 in")
  dimension "d297" radius A31 = 1.5875 (= "d296")
  dimension "d298" radius A33 = 0.3969 (= "( 1 / 64 ) * 1 in")
  dimension "d299" radius A34 = 0.3969 (= "( 1 / 64 ) * 1 in")
  dimension "d300" radius A35 = 0.3969 (= "( 1 / 64 ) * 1 in")
  dimension "d301" radius A36 = 0.3969 (= "d300")
  dimension "d302" radius = 0.4047 (= "d290")
  dimension "d303" radius A37 = 0.4047 (= "d302")
  dimension "d304" distance L40 L42 = 1.1753 (= "d305")
  dimension "d305" distance L28 L31 = 1.1753
  dimension "d306" distance L39 L43 = 1.1753 (= "d305")
  dimension "d307" radius = 0.3969 (= "( 1 / 64 ) * 1 in")
  dimension "d308" radius = 0.3969 (= "d307")
  dimension "d309" distance L44 L46 = 1.5875 (= "( 1 / 16 ) * 1 in")
  dimension "d310" radius = 0.7937 (= "( 1 / 32 ) * 1 in")
  dimension "d311" radius = 0.3969 (= "( 1 / 64 ) * 1 in")
  dimension "d312" radius = 0.3969 (= "( 1 / 64 ) * 1 in")
  dimension "d313" distance L47 L49 = 1.5875 (= "( 1 / 16 ) * 1 in")
  dimension "d314" radius = 0.3969 (= "( 1 / 64 ) * 1 in")
  dimension "d317" radius = 0.3969 (= "( 1 / 64 ) * 1 in")
  dimension "d318" angle L50 L51 = 109
  dimension "d319" radius = 0.3969 (= "( 1 / 64 ) * 1 in")
  dimension "d320" distance L50 L52 = 1.5875 (= "( 1 / 16 ) * 1 in")
  dimension "d321" radius = 0.3969 (= "( 1 / 64 ) * 1 in")
  dimension "d322" radius = 0.3969 (= "( 1 / 64 ) * 1 in")
  dimension "d323" angle L50 L53 = 109
  dimension "d324" radius = 0.7937 (= "( 1 / 32 ) * 1 in")
  dimension "d326" radius = 0.3969 (= "( 1 / 64 ) * 1 in")
  dimension "d327" radius = 0.3969 (= "( 1 / 64 ) * 1 in")
  dimension "d328" distance L55 L57 = 1.5875 (= "( 1 / 16 ) * 1 in")
  dimension "d329" distance L54 L58 = 1.7223 (= "d278")
  dimension "d330" radius = 0.3969 (= "( 1 / 64 ) * 1 in")
  dimension "d331" radius = 0.3969 (= "d330")
  dimension "d332" distance L58 L60 = 1.3496
  dimension "d333" radius = 0.3969 (= "d330")
  dimension "d334" distance L59 L61 = 1.5875 (= "( 1 / 16 ) * 1 in")
  dimension "d335" radius = 0.3969 (= "d330")
  dimension "d336" radius = 0.3969 (= "( 1 / 64 ) * 1 in")
  dimension "d337" radius = 0.3969 (= "d336")
  dimension "d338" radius = 0.3969 (= "d337")
  dimension "d339" angle L64 L65 = 114.659
  dimension "d340" radius = 0.3969 (= "( 1 / 64 ) * 1 in")
  dimension "d342" distance L64 L66 = 1.5875 (= "( 1 / 16 ) * 1 in")
  dimension "d408" distance L68 L75 = 3.175 (= "( 1 / 8 ) * 1 in")
  dimension "d411" distance P216 P219 = 1.1906 (= "( 3 / 64 ) * 1 in")
  dimension "d412" distance L75 L76 = 1.5875 (= "( 1 / 16 ) * 1 in")
  dimension "d406" Text1-Height = 11.1125 (= "( 7 / 16 ) * 1 in")
extrude "Extrude18" add sketch "Text Profile 1" along normal blind 0.3969 (= "( 1 / 64 ) * 1 in") taper -30
extrude "Extrude20" add sketch "Text Profile 1" profile of L76 L77 L78 L79 along normal blind 0.3969 (= "( 1 / 64 ) * 1 in") taper -25
sketch "Text Profile 2" plane through (0, 3.9688, 0) normal (0, 1, 0) x axis (-1, 0, 0)
  line L1 (-12.7, 174.625) -> (-12.7, 165.6244)
  line L2 (-6.35, 247.65) -> (-6.35, 183.6053)
  line L3 (-107.95, 247.65) -> (-6.35, 247.65)
  line L4 (-107.95, 241.8244) -> (-107.95, 247.65)
  line L5 (-19.05, 227.0125) -> (-87.049, 227.0125)
  line L6 (-14.2875, 165.7971) -> (-14.2875, 222.25)
  line L7 (51.6936, 232.5688) -> (14.329, 232.5688)
  line L8 (14.329, 232.5688) -> (14.329, 231.3781)
  line L9 (97.2243, 234.1562) -> (6.35, 234.1563)
  line L10 (87.049, 227.0125) -> (19.05, 227.0125)
  line L11 (14.329, 237.3313) -> (14.329, 232.5688)
  line L12 (-35.0916, 228.6606) -> (-35.0916, 229.534)
  line L13 (-56.5279, 232.1884) -> (-56.5279, 231.7331)
  line L14 (-55.1727, 240.0742) -> (-55.1727, 242.6195)
  line L15 (-53.3927, 241.9401) -> (-52.7963, 241.9401)
  line L16 (-56.9292, 231.2025) -> (-60.5046, 230.1902)
  line L17 (-63.246, 229.362) -> (-66.1059, 227.9048)
  line L18 (-64.8931, 230.4242) -> (-63.7672, 230.9979)
  line L19 (-54.2924, 235.8003) -> (-54.6739, 235.8003)
  line L20 (-58.8781, 242.4647) -> (-57.4713, 242.1229)
  line L21 (-58.9124, 232.1919) -> (-57.1809, 232.6822)
  line L22 (-59.285, 236.5428) -> (-58.9219, 236.5428)
  line L23 (-52.2646, 233.2425) -> (-52.2646, 235.4298)
  line L24 (-65.9127, 246.1956) -> (-66.5663, 246.6533)
  line L25 (-41.3385, 244.2212) -> (-41.3385, 230.856)
  line L26 (-36.4594, 236.9344) -> (-36.4594, 237.7281)
  line L27 (-57.2043, 243.6243) -> (-60.706, 244.475)
  line L28 (-58.9219, 238.1303) -> (-59.285, 238.1303)
  line L29 (-51.4611, 243.1154) -> (-54.6768, 243.1154)
  line L30 (-49.1272, 232.4584) -> (-49.1272, 242.9431)
  line L31 (-53.7974, 240.886) -> (-53.7974, 241.3086)
  line L32 (-47.5397, 233.5088) -> (-47.5397, 242.9431)
  line L33 (-51.0453, 241.0963) -> (-51.0453, 242.6995)
  line L34 (-53.7974, 241.3086) -> (-53.7974, 241.5354)
  line L35 (-59.7945, 238.6398) -> (-59.7945, 241.7443)
  line L36 (-56.7698, 242.6744) -> (-56.7698, 243.0716)
  line L37 (-37.809, 231.2905) -> (-37.809, 236.1406)
  line L38 (-37.809, 238.5219) -> (-37.809, 236.1406)
  line L39 (-37.4121, 236.5375) -> (-36.8562, 236.5375)
  line L40 (-39.5313, 230.589) -> (-39.5313, 244.9325)
  line L41 (-42.926, 231.1293) -> (-42.926, 243.9479)
  line L42 (-47.1922, 233.115) -> (-44.7766, 232.8117)
  line L43 (-36.8562, 238.125) -> (-37.4121, 238.125)
  line L44 (-35.7413, 247.0593) -> (-39.0463, 245.6637)
  line L45 (-35.19, 245.832) -> (-35.19, 246.6936)
  line L46 (-37.809, 238.5219) -> (-37.809, 244.1998)
  line L47 (-44.4292, 232.4179) -> (-44.4292, 231.6179)
  line L48 (-35.3229, 229.8947) -> (-37.5777, 230.9299)
  line L49 (-42.6583, 244.3232) -> (-41.8646, 244.5965)
  line L50 (-39.0687, 229.8676) -> (-35.654, 228.3)
  line L51 (-44.8755, 231.2241) -> (-48.4323, 231.6708)
  line L52 (-47.9365, 243.34) -> (-48.7303, 243.34)
  line L53 (-41.8646, 230.4807) -> (-42.6583, 230.754)
  line L54 (-37.5665, 244.5654) -> (-35.4325, 245.4664)
  line L55 (51.6936, 237.3313) -> (51.6936, 232.5688)
  line L56 (51.6936, 231.3781) -> (51.6936, 232.5688)
  line L57 (14.329, 231.3781) -> (51.6936, 231.3781)
  line L58 (-53.0495, 247.65) -> (-53.0495, 227.0125)
  line L59 (-58.4124, 237.0523) -> (-58.4124, 237.6208)
  line L60 (-65.6999, 230.9186) -> (-65.6999, 245.7868)
  line L61 (-50.6771, 232.0593) -> (-50.6771, 235.9578)
  line L62 (-50.9933, 236.9085) -> (-53.6609, 240.4755)
  line L63 (-52.5808, 236.3806) -> (-55.0362, 239.6637)
  line L64 (-67.4223, 228.7115) -> (-67.4223, 246.2077)
  line L65 (-52.6693, 232.8378) -> (-53.4908, 232.8378)
  line L66 (-53.8955, 233.2425) -> (-53.8955, 235.4034)
  line L67 (-54.6739, 231.6625) -> (-51.074, 231.6625)
  line L68 (-55.0708, 235.4034) -> (-55.0708, 232.0593)
  line L69 (-62.8318, 230.4246) -> (-62.8318, 230.0379)
  line L70 (-59.7945, 232.8589) -> (-59.7945, 236.0333)
  line L71 (-61.382, 230.8537) -> (-61.382, 243.9436)
  line L72 (-59.7945, 238.6398) -> (-59.7945, 236.0333)
  line L73 (-12.7, 174.625) -> (-12.7, 165.6244)
  line L74 (-6.35, 247.65) -> (-6.35, 183.6053)
  line L75 (-107.95, 247.65) -> (-6.35, 247.65)
  line L76 (-107.95, 241.8244) -> (-107.95, 247.65)
  line L77 (-22.225, 227.0125) -> (-80.9625, 227.0125)
  line L78 (-14.2875, 165.7971) -> (-14.2875, 219.075)
  line L79 (-52.3968, 241.6002) -> (-52.2986, 240.9952)
  line L80 (-88.9, 219.075) -> (-88.9, 212.725)
  arc A1 centre (-19.05, 165.7971) radius 4.7625 clockwise from (-14.2875, 165.7971) to (-14.3871, 164.8283)
  arc A2 centre (0, 136.525) radius 31.75 clockwise from (-14.3871, 164.8283) to (-12.7, 165.6244)
  arc A3 centre (-3.175, 174.625) radius 9.525 clockwise from (-12.7, 174.625) to (-6.35, 183.6053)
  arc A4 centre (-120.65, 212.725) radius 31.75 clockwise from (-107.95, 241.8244) to (-91.1989, 224.5865)
  arc A5 centre (-87.049, 222.25) radius 4.7625 clockwise from (-91.1989, 224.5865) to (-87.049, 227.0125)
  arc A6 centre (-19.05, 222.25) radius 4.7625 clockwise from (-19.05, 227.0125) to (-14.2875, 222.25)
  arc A7 centre (19.05, 222.25) radius 4.7625 clockwise from (14.2875, 222.25) to (19.05, 227.0125)
  arc A8 centre (-19.05, 222.25) radius 4.7625 clockwise from (-19.05, 227.0125) to (-14.2875, 222.25)
  arc A9 centre (87.049, 222.25) radius 4.7625 clockwise from (87.049, 227.0125) to (91.1989, 224.5865)
  arc A10 centre (-63.4751, 230.4246) radius 0.6433 clockwise from (-63.7672, 230.9979) to (-62.8318, 230.4246)
  arc A11 centre (-66.1989, 245.7868) radius 0.499 clockwise from (-65.9127, 246.1956) to (-65.6999, 245.7868)
  arc A12 centre (-54.6739, 232.0593) radius 0.3969 clockwise from (-54.6739, 231.6625) to (-55.0708, 232.0593)
  arc A13 centre (-60.6924, 230.8537) radius 0.6896 clockwise from (-60.5046, 230.1902) to (-61.382, 230.8537)
  arc A14 centre (-59.285, 236.0333) radius 0.5095 clockwise from (-59.7945, 236.0333) to (-59.285, 236.5428)
  arc A15 centre (-57.0794, 231.7331) radius 0.5515 clockwise from (-56.5279, 231.7331) to (-56.9292, 231.2025)
  arc A16 centre (-52.6693, 233.2425) radius 0.4047 clockwise from (-52.2646, 233.2425) to (-52.6693, 232.8378)
  arc A17 centre (-53.3927, 241.5354) radius 0.4047 clockwise from (-53.7974, 241.5354) to (-53.3927, 241.9401)
  arc A18 centre (-53.8521, 235.4298) radius 1.5875 clockwise from (-52.5808, 236.3806) to (-52.2646, 235.4298)
  arc A19 centre (-54.2924, 235.4034) radius 0.3969 clockwise from (-54.2924, 235.8003) to (-53.8955, 235.4034)
  arc A20 centre (-59.1013, 232.8589) radius 0.6932 clockwise from (-58.9124, 232.1919) to (-59.7945, 232.8589)
  arc A21 centre (-66.5169, 228.7115) radius 0.9053 clockwise from (-66.1059, 227.9048) to (-67.4223, 228.7115)
  arc A22 centre (-63.5904, 230.0379) radius 0.7586 clockwise from (-62.8318, 230.0379) to (-63.246, 229.362)
  arc A23 centre (-54.6739, 235.4034) radius 0.3969 clockwise from (-55.0708, 235.4034) to (-54.6739, 235.8003)
  arc A24 centre (-58.9219, 237.6208) radius 0.5095 clockwise from (-58.9219, 238.1303) to (-58.4124, 237.6208)
  arc A25 centre (-59.285, 238.6398) radius 0.5095 clockwise from (-59.285, 238.1303) to (-59.7945, 238.6398)
  arc A26 centre (-66.8783, 246.2077) radius 0.5439 clockwise from (-67.4223, 246.2077) to (-66.5663, 246.6533)
  arc A27 centre (-57.3373, 242.6744) radius 0.5676 clockwise from (-56.7698, 242.6744) to (-57.4713, 242.1229)
  arc A28 centre (-51.676, 241.0963) radius 0.6307 clockwise from (-51.0453, 241.0963) to (-52.2986, 240.9952)
  arc A29 centre (-54.4873, 240.0742) radius 0.6854 clockwise from (-55.0362, 239.6637) to (-55.1727, 240.0742)
  arc A30 centre (-59.0531, 241.7443) radius 0.7413 clockwise from (-59.7945, 241.7443) to (-58.8781, 242.4647)
  arc A31 centre (-53.112, 240.886) radius 0.6854 clockwise from (-53.6609, 240.4755) to (-53.7974, 240.886)
  arc A32 centre (-54.6768, 242.6195) radius 0.4959 clockwise from (-55.1727, 242.6195) to (-54.6768, 243.1154)
  arc A33 centre (-52.7963, 241.5354) radius 0.4047 clockwise from (-52.7963, 241.9401) to (-52.3968, 241.6002)
  arc A34 centre (-57.3386, 243.0716) radius 0.5688 clockwise from (-57.2043, 243.6243) to (-56.7698, 243.0716)
  arc A35 centre (-60.8351, 243.9436) radius 0.5469 clockwise from (-61.382, 243.9436) to (-60.706, 244.475)
  arc A36 centre (-51.4611, 242.6995) radius 0.4159 clockwise from (-51.4611, 243.1154) to (-51.0453, 242.6995)
  arc A37 centre (-36.8562, 236.9344) radius 0.3969 clockwise from (-36.4594, 236.9344) to (-36.8562, 236.5375)
  arc A38 centre (-44.8261, 231.6179) radius 0.3969 clockwise from (-44.4292, 231.6179) to (-44.8755, 231.2241)
  arc A39 centre (-38.7375, 230.589) radius 0.7938 clockwise from (-39.0687, 229.8676) to (-39.5313, 230.589)
  arc A40 centre (-41.7354, 230.856) radius 0.3969 clockwise from (-41.3385, 230.856) to (-41.8646, 230.4807)
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  point P44 (-65.6999, 230.9186)
  point P76 (-65.6999, 230.9186)
  point P163 (-47.5397, 233.5088)
  point P191 (-47.5397, 233.5088)
  point P208 (-36.4594, 237.3313)
  point P179 (-39.5313, 230.589)
  point P188 (-39.5313, 230.589)
  point P22 (14.329, 232.5688)
  point P23 (14.329, 231.3781)
  tangent A26 L64
  tangent L24 A26
  tangent A11 L24
  tangent A11 L60
  vertical L60
  tangent A21 L64
  tangent L17 A21
  tangent L17 A22
  vertical L69
  tangent A22 L69
  tangent A10 L69
  tangent A10 L18
  parallel L17 L18
  coincident P44 P76
  vertical L71
  tangent A35 L71
  tangent L27 A35
  tangent L27 A34
  tangent A34 L36
  vertical L36
  tangent A27 L36
  tangent L20 A27
  parallel L20 L27
  tangent L20 A30
  vertical L35
  tangent A30 L35
  tangent A25 L35
  tangent A25 L28
  horizontal L28
  tangent A24 L28
  tangent A24 L59
  vertical L59
  horizontal L22
  tangent A14 L22
  vertical L70
  tangent A14 L70
  vertical L72
  tangent A13 L71
  tangent A13 L16
  tangent A15 L16
  vertical L13
  tangent L13 A15
  tangent A20 L21
  tangent A20 L70
  parallel L16 L21
  vertical L61
  tangent A18 L63
  tangent A18 L23
  vertical L23
  horizontal L67
  tangent A12 L67
  vertical L68
  tangent A12 L68
  tangent A23 L68
  horizontal L19
  tangent L19 A23
  tangent A19 L19
  vertical L66
  tangent A19 L66
  tangent A16 L23
  perpendicular L58 L65
  tangent A16 L65
  vertical L30
  horizontal L52
  vertical L32
  tangent A38 L51
  vertical L47
  tangent A38 L47
  parallel L42 L51
  coincident P163 P191
  vertical L41
  tangent A40 L53
  vertical L25
  tangent L25 A40
  vertical L45
  parallel L44 L54
  vertical L46
  horizontal L43
  vertical L26
  tangent L26 A37
  horizontal L39
  tangent A37 L39
  vertical L37
  vertical L38
  midpoint P208 L26
  vertical L12
  parallel L48 L50
  tangent A39 L50
  coincident P179 P188
  tangent A39 L40
  horizontal L7
  vertical L56
  horizontal L57
  vertical L8
  tangent A28 L79
  dimension "d414" angle L24 L64 = 55
  dimension "d415" distance L60 L64 = 1.7223
  dimension "d416" angle L17 L64 = 63
  dimension "d417" distance L35 L71 = 1.5875 (= "( 1 / 16 ) * 1 in")
  dimension "d418" radius A24 = 0.5095
  dimension "d419" radius A25 = 0.5095 (= "d281")
  dimension "d420" radius = 0.5095 (= "d281")
  dimension "d421" radius A14 = 0.5095 (= "d281")
  dimension "d422" distance L22 L28 = 1.5875 (= "( 1 / 16 ) * 1 in")
  dimension "d443" radius = 0.3969 (= "( 1 / 64 ) * 1 in")
  dimension "d444" radius = 0.3969 (= "d307")
  dimension "d445" distance L30 L32 = 1.5875 (= "( 1 / 16 ) * 1 in")
  dimension "d446" radius = 0.7937 (= "( 1 / 32 ) * 1 in")
  dimension "d447" radius A38 = 0.3969 (= "( 1 / 64 ) * 1 in")
  dimension "d448" radius = 0.3969 (= "( 1 / 64 ) * 1 in")
  dimension "d449" distance L42 L51 = 1.5875 (= "( 1 / 16 ) * 1 in")
  dimension "d450" radius = 0.3969 (= "( 1 / 64 ) * 1 in")
  dimension "d451" radius = 0.3969 (= "( 1 / 64 ) * 1 in")
  dimension "d452" angle L41 L53 = 109
  dimension "d453" radius A40 = 0.3969 (= "( 1 / 64 ) * 1 in")
  dimension "d454" distance L25 L41 = 1.5875 (= "( 1 / 16 ) * 1 in")
  dimension "d455" radius = 0.3969 (= "( 1 / 64 ) * 1 in")
  dimension "d456" radius = 0.3969 (= "( 1 / 64 ) * 1 in")
  dimension "d457" angle L41 L49 = 109
  dimension "d458" radius = 0.7937 (= "( 1 / 32 ) * 1 in")
  dimension "d459" radius = 0.3969 (= "( 1 / 64 ) * 1 in")
  dimension "d460" radius = 0.3969 (= "( 1 / 64 ) * 1 in")
  dimension "d461" distance L44 L54 = 1.5875 (= "( 1 / 16 ) * 1 in")
  dimension "d462" distance L40 L46 = 1.7223 (= "d278")
  dimension "d463" radius = 0.3969 (= "( 1 / 64 ) * 1 in")
  dimension "d464" radius = 0.3969 (= "d330")
  dimension "d465" distance L26 L46 = 1.3496
  dimension "d466" radius A37 = 0.3969 (= "d330")
  dimension "d467" distance L39 L43 = 1.5875 (= "( 1 / 16 ) * 1 in")
  dimension "d468" radius = 0.3969 (= "d330")
  dimension "d469" radius = 0.3969 (= "( 1 / 64 ) * 1 in")
  dimension "d470" radius = 0.3969 (= "d336")
  dimension "d471" radius = 0.3969 (= "d337")
  dimension "d472" angle L12 L48 = 114.659
  dimension "d473" radius = 0.3969 (= "( 1 / 64 ) * 1 in")
  dimension "d474" distance L48 L50 = 1.5875 (= "( 1 / 16 ) * 1 in")
  dimension "d475" distance P22 P23 = 1.1906 (= "( 3 / 64 ) * 1 in")
  dimension "d476" distance L7 L9 = 1.5875 (= "( 1 / 16 ) * 1 in")
  dimension "d413" Text1-Height = 11.1125 (= "( 7 / 16 ) * 1 in")
extrude "Extrude21" add sketch "Text Profile 2" profile of L7 L8 L56 L57 along normal blind 0.3969 (= "( 1 / 64 ) * 1 in") taper -25
extrude "Extrude22" add sketch "Text Profile 2" along normal blind 0.3969 (= "( 1 / 64 ) * 1 in") taper -30
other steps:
create_component "CreateComponent1"
named bodies: "26091 Five Horn Base", "Plug Weld"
